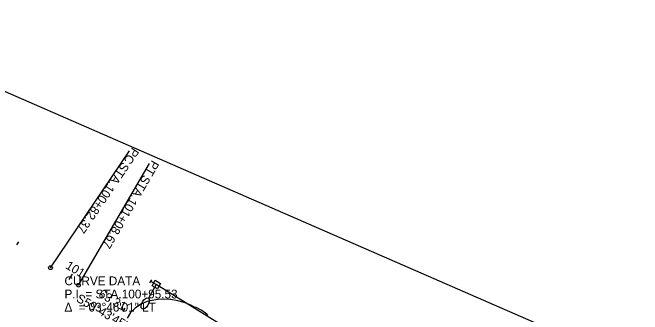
# Model space of a CAD drawing. Extents: x 1598538 to 1602183, y 285823 to 288192.
# Drawn here: x 1600742 to 1601244, y 286869 to 287110 of the extents above; entities that cross this region are included whole.
import ezdxf

# ---------------------------------------------------------------- set-up
doc = ezdxf.new("R2010")
doc.units = 0
for name, color, linetype in [('CM_Corridor_Conceptual', 7, 'Continuous'), ('CM_Corridor_Range_Conceptual', 7, 'Continuous'), ('Default', 7, 'Continuous'), ('MD_P_ACSC_B', 7, 'Continuous'), ('MD_P_AGB_B', 7, 'Continuous'), ('PV_P_Curb', 7, 'Continuous'), ('PV_P_EOP', 7, 'Continuous'), ('RW_P_Esmt_LA', 7, 'Continuous'), ('RW_P_Esmt_TMP', 7, 'Continuous')]:
    doc.layers.add(name, color=color, linetype=linetype)

msp = doc.modelspace()

# ---------------------------------------------------------------- linework, layer by layer
at = {"layer": 'Default'}
msp.add_lwpolyline([(1600898.05, 286868.65), (1600897.17, 286869.36), (1600893.05, 286872.3), (1600888.55, 286874.71), (1600887.42, 286875.18), (1600883.92, 286876.93), (1600879.05, 286878.8), (1600873.92, 286880.24), (1600868.55, 286881.24), (1600867.67, 286881.27), (1600862.8, 286881.52), (1600858.05, 286881.24), (1600856.55, 286881.05), (1600850.55, 286879.83), (1600849.55, 286879.46), (1600844.55, 286877.52), (1600840.8, 286874.93), (1600839.92, 286874.36), (1600836.17, 286870.71), (1600833.67, 286866.3)], dxfattribs=at)
at = {"layer": 'MD_P_ACSC_B'}
msp.add_line((1600591.71, 287110.09), (1601244.34, 286825.47), dxfattribs=at)
at = {"layer": 'MD_P_AGB_B'}
for p, q in [((1600745.7, 286924.68), (1600747.38, 286927.16)), ((1600787.35, 286897.02), (1600789.96, 286901.28)), ((1600830.49, 286871.73), (1600832, 286874.32))]:
    msp.add_line(p, q, dxfattribs=at)
at = {"layer": 'PV_P_Curb'}
for p, q in [((1600772.53, 286906.56), (1600835.5, 286999.78)), ((1600794.79, 286892.56), (1600851.5, 286989.72))]:
    msp.add_line(p, q, dxfattribs=at)
for centre in [(1600772.53, 286906.56), (1600794.79, 286892.56)]:
    msp.add_circle(centre, 1.5, dxfattribs=at)
at = {"layer": 'RW_P_Esmt_LA'}
msp.add_line((1600856.86, 286893.09), (1600850.58, 286882.28), dxfattribs=at)
msp.add_lwpolyline([(1600860.28, 286894), (1600857.76, 286889.67), (1600853.44, 286892.19), (1600855.95, 286896.51)], close=True, dxfattribs=at)
msp.add_ellipse((1600848.06, 286877.96), major_axis=(-2.51, -4.32), ratio=0.5, dxfattribs=at)
at = {"layer": 'RW_P_Esmt_TMP'}
for p, q in [((1600851.81, 286894.35), (1600853.31, 286896.94)), ((1600856.86, 286893.09), (1600852.57, 286895.66)), ((1601041.07, 286779.12), (1600856.86, 286893.09))]:
    msp.add_line(p, q, dxfattribs=at)

# ---------------------------------------------------------------- texts
at = {"layer": 'CM_Corridor_Conceptual'}
for s, p in [('CURVE DATA', (1600783.66, 286892.56)), ('P.I. = STA. ', (1600783.66, 286882.06)), ('100+95.53', (1600829.33, 286882.06)), ('Δ  = ', (1600783.66, 286871.56)), ('03°46\'01" LT', (1600802.85, 286871.56))]:
    msp.add_text(s, height=7, dxfattribs=at).set_placement(p)
at = {"layer": 'CM_Corridor_Range_Conceptual'}
msp.add_text("63.31'", height=7, rotation=329.7293, dxfattribs=at).set_placement((1600810.17, 286883.71))
at = {"layer": 'MD_P_AGB_B'}
msp.add_text('101', height=7, rotation=328.4871, dxfattribs=at).set_placement((1600783.9, 286906.46))
at = {"layer": 'PV_P_Curb'}
for s, rotation, p in [('PC', 235.9623, (1600837.77, 287002.96)), ('PT', 239.7293, (1600853.45, 286992.86)), (' STA. ', 235.9623, (1600831.36, 286993.46)), (' STA. ', 239.7293, (1600847.89, 286983.33)), ('100+82.37', 235.9623, (1600818.13, 286973.88)), ('101+08.67', 239.7293, (1600835.98, 286962.92))]:
    msp.add_text(s, height=7, rotation=rotation, dxfattribs=at).set_placement(p)
at = {"layer": 'PV_P_EOP'}
msp.add_text('S59°43\'45"E', height=7, rotation=329.7293, dxfattribs=at).set_placement((1600792.46, 286880.03))

doc.saveas('drawing.dxf')
